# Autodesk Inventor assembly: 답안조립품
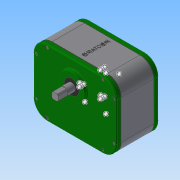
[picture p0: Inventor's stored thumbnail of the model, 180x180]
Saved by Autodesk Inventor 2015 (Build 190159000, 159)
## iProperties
Created: 2020-03
Part Number: 답안조립품
Document SubType Name: Assembly
Designer: user
Author: user
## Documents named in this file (13)
- C:\Users\user\Desktop\600306V1013\답안조립품.iam
- C:\Users\user\Desktop\600306V1013\본체.ipt
- C:\Users\user\Desktop\600306V1013\개스킷.ipt
- C:\Users\user\Desktop\600306V1013\앞커버.ipt
- C:\Users\user\Desktop\600306V1013\뒤커버.ipt
- C:\Users\user\Desktop\600306V1013\베어링 6003.ipt
- C:\Users\user\Desktop\600306V1013\베어링 608.ipt
- C:\Users\user\Desktop\600306V1013\오일실 17 32 8.ipt
- C:\Users\user\Desktop\600306V1013\오일실 8 22 7.ipt
- C:\Users\user\Desktop\600306V1013\메인축.ipt
- C:\Users\user\Desktop\600306V1013\서브축 A.ipt
- C:\Users\user\Desktop\600306V1013\서브축 B.ipt
- C:\Users\user\Desktop\600306V1013\볼트 M4.ipt
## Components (2 placed, 1 different names)
1. 개스킷:1
2. 개스킷:2
